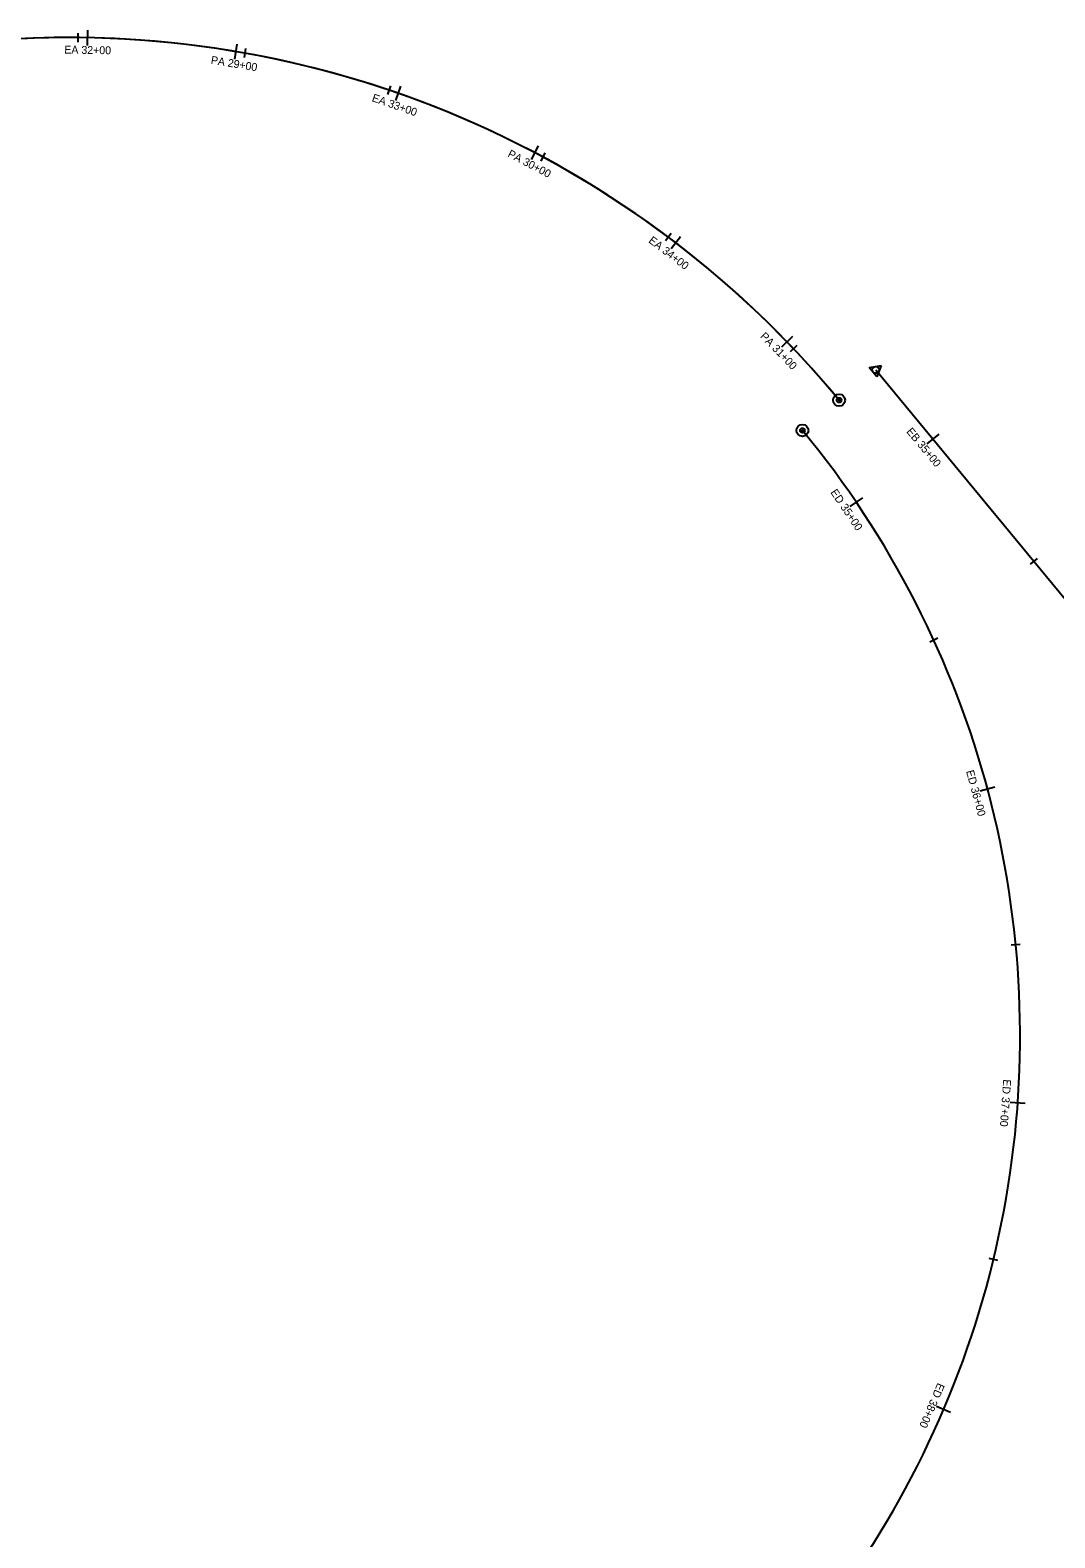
# Model space of a CAD drawing. Extents: x 950864 to 953360, y 1126381 to 1128045.
# Drawn here: x 952285.2 to 952608.5, y 1127568.8 to 1128044.6 of the extents above; entities that cross this region are included whole.
import ezdxf

# ---------------------------------------------------------------- set-up
doc = ezdxf.new("R2010")
doc.units = 0
doc.layers.add('Existing', color=7, linetype='Continuous')
doc.layers.add('Proposed', color=7, linetype='Continuous')

msp = doc.modelspace()

# ---------------------------------------------------------------- linework, layer by layer
at = {"layer": 'Existing'}
msp.add_line((952552.01, 1127937.37), (952686.91, 1127774.04), dxfattribs=at)
for points in [[(952303.27, 1128044.56), (952303.18, 1128039.76)], [(952353.19, 1128038.73), (952352.69, 1128035.89)], [(952402.05, 1128026.93), (952400.47, 1128022.4)], [(952447.65, 1128005.8), (952446.29, 1128003.27)], [(952490.39, 1127979.34), (952487.47, 1127975.53)], [(952527.12, 1127945.03), (952525.03, 1127943.05)], [(952549.96, 1127938.13), (952553.69, 1127938.76)], [(952552.37, 1127935.22), (952549.96, 1127938.13)], [(952553.69, 1127938.76), (952552.37, 1127935.22)], [(952571.89, 1127917.06), (952568.19, 1127914.01)], [(952547.84, 1127896.96), (952543.87, 1127894.26)], [(952603, 1127877.9), (952600.78, 1127876.07)], [(952571.66, 1127852.69), (952569.04, 1127851.49)], [(952589.61, 1127805.73), (952584.97, 1127804.48)], [(952597.63, 1127756.1), (952594.76, 1127755.83)], [(952599.22, 1127705.86), (952594.44, 1127706.2)], [(952590.57, 1127656.34), (952587.77, 1127657.01)], [(952575.63, 1127608.34), (952571.22, 1127610.22)]]:
    msp.add_lwpolyline(points, dxfattribs=at)
for centre, radius in [((952552.01, 1127937.37), 1.09), ((952540.45, 1127927.81), 1.89), ((952540.45, 1127927.81), 0.744), ((952540.45, 1127927.81), 0.154), ((952528.88, 1127918.26), 1.88), ((952528.88, 1127918.26), 0.747), ((952528.88, 1127918.26), 0.156)]:
    msp.add_circle(centre, radius, dxfattribs=at)
for radius, start, end in [(315, 39.5561, 189.4135), (300, 300.7397, 39.5561)]:
    msp.add_arc((952297.58, 1127727.21), radius, start, end, dxfattribs=at)
at = {"layer": 'Proposed'}
for points in [[(952300.28, 1128043.64), (952300.25, 1128040.76)], [(952350.42, 1128040.18), (952349.62, 1128035.45)], [(952398.92, 1128026.99), (952397.99, 1128024.26)], [(952445.47, 1128008.05), (952443.24, 1128003.8)], [(952487.43, 1127980.38), (952485.7, 1127978.07)], [(952525.75, 1127947.85), (952522.3, 1127944.52)]]:
    msp.add_lwpolyline(points, dxfattribs=at)
for radius in [1.89, 0.744, 0.154]:
    msp.add_circle((952540.45, 1127927.81), radius, dxfattribs=at)
msp.add_arc((952297.58, 1127727.21), 315, 39.5561, 151.7306, dxfattribs=at)

# ---------------------------------------------------------------- texts
at = {"layer": 'Existing'}
for s, rotation, p in [('EA 32+00', 358.9724, (952295.95, 1128037.2)), ('EA 33+00', 340.7833, (952392.83, 1128022.21)), ('EA 34+00', 322.5942, (952480.12, 1127977.76)), ('EB 35+00', 309.5561, (952561.54, 1127917.84)), ('ED 35+00', 304.1475, (952537.61, 1127898.71)), ('ED 36+00', 285.0489, (952580.51, 1127810.72)), ('ED 37+00', 265.9503, (952592.26, 1127713.57)), ('ED 38+00', 246.8517, (952571.58, 1127617.9))]:
    msp.add_text(s, height=2.496, rotation=rotation, dxfattribs=at).set_placement(p)
at = {"layer": 'Proposed'}
for s, rotation, p in [('PA 29+00', 350.417, (952342.08, 1128034)), ('PA 30+00', 332.2279, (952435.65, 1128004.76)), ('PA 31+00', 314.0387, (952515.39, 1127947.79))]:
    msp.add_text(s, height=2.496, rotation=rotation, dxfattribs=at).set_placement(p)

doc.saveas('drawing.dxf')
